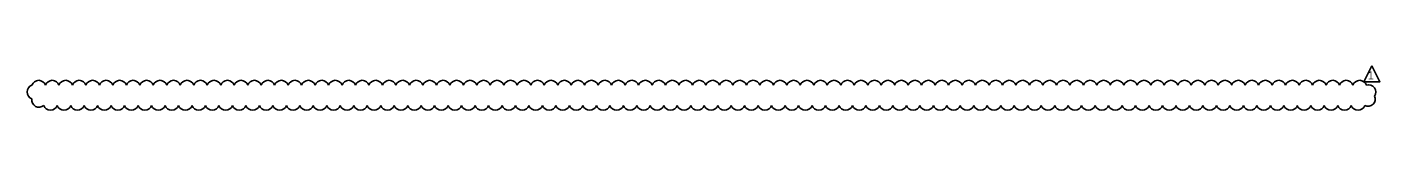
# Model space of a CAD drawing. Extents: x -156 to 77, y 0 to 24.
# Drawn here: x -156.35 to -132.68, y 23.65 to 24.43 of the extents above; entities that cross this region are included whole.
import ezdxf

# ---------------------------------------------------------------- set-up
doc = ezdxf.new("R2010")
doc.units = 0
doc.layers.add('SH_Text', color=7, linetype='Continuous')

msp = doc.modelspace()

# ---------------------------------------------------------------- linework, layer by layer
at = {"layer": 'SH_Text'}
msp.add_lwpolyline([(-132.816, 24.427), (-132.956, 24.147), (-132.676, 24.147)], close=True, dxfattribs=at)
for centre, start, end in [((-156.146, 24.047), 17.5, 162.5), ((-155.91, 24.047), 17.5, 162.5), ((-155.674, 24.047), 17.5, 162.5), ((-155.438, 24.047), 17.5, 162.5), ((-155.203, 24.047), 17.5, 162.5), ((-154.967, 24.047), 17.5, 162.5), ((-154.731, 24.047), 17.5, 162.5), ((-154.495, 24.047), 17.5, 162.5), ((-154.259, 24.047), 17.5, 162.5), ((-154.023, 24.047), 17.5, 162.5), ((-153.787, 24.047), 17.5, 162.5), ((-153.551, 24.047), 17.5, 162.5), ((-153.316, 24.047), 17.5, 162.5), ((-153.08, 24.047), 17.5, 162.5), ((-152.844, 24.047), 17.5, 162.5), ((-152.608, 24.047), 17.5, 162.5), ((-152.372, 24.047), 17.5, 162.5), ((-152.136, 24.047), 17.5, 162.5), ((-151.9, 24.047), 17.5, 162.5), ((-151.664, 24.047), 17.5, 162.5), ((-151.428, 24.047), 17.5, 162.5), ((-151.193, 24.047), 17.5, 162.5), ((-150.957, 24.047), 17.5, 162.5), ((-150.721, 24.047), 17.5, 162.5), ((-150.485, 24.047), 17.5, 162.5), ((-150.249, 24.047), 17.5, 162.5), ((-150.013, 24.047), 17.5, 162.5), ((-149.777, 24.047), 17.5, 162.5), ((-149.541, 24.047), 17.5, 162.5), ((-149.306, 24.047), 17.5, 162.5), ((-149.07, 24.047), 17.5, 162.5), ((-148.834, 24.047), 17.5, 162.5), ((-148.598, 24.047), 17.5, 162.5), ((-148.362, 24.047), 17.5, 162.5), ((-148.126, 24.047), 17.5, 162.5), ((-147.89, 24.047), 17.5, 162.5), ((-147.654, 24.047), 17.5, 162.5), ((-147.418, 24.047), 17.5, 162.5), ((-147.183, 24.047), 17.5, 162.5), ((-146.947, 24.047), 17.5, 162.5), ((-146.711, 24.047), 17.5, 162.5), ((-146.475, 24.047), 17.5, 162.5), ((-146.239, 24.047), 17.5, 162.5), ((-146.003, 24.047), 17.5, 162.5), ((-145.767, 24.047), 17.5, 162.5), ((-145.531, 24.047), 17.5, 162.5), ((-145.296, 24.047), 17.5, 162.5), ((-145.06, 24.047), 17.5, 162.5), ((-144.824, 24.047), 17.5, 162.5), ((-144.588, 24.047), 17.5, 162.5), ((-144.352, 24.047), 17.5, 162.5), ((-144.116, 24.047), 17.5, 162.5), ((-143.88, 24.047), 17.5, 162.5), ((-143.644, 24.047), 17.5, 162.5), ((-143.408, 24.047), 17.5, 162.5), ((-143.173, 24.047), 17.5, 162.5), ((-142.937, 24.047), 17.5, 162.5), ((-142.701, 24.047), 17.5, 162.5), ((-142.465, 24.047), 17.5, 162.5), ((-142.229, 24.047), 17.5, 162.5), ((-141.993, 24.047), 17.5, 162.5), ((-141.757, 24.047), 17.5, 162.5), ((-141.521, 24.047), 17.5, 162.5), ((-141.286, 24.047), 17.5, 162.5), ((-141.05, 24.047), 17.5, 162.5), ((-140.814, 24.047), 17.5, 162.5), ((-140.578, 24.047), 17.5, 162.5), ((-140.342, 24.047), 17.5, 162.5), ((-140.106, 24.047), 17.5, 162.5), ((-139.87, 24.047), 17.5, 162.5), ((-139.634, 24.047), 17.5, 162.5), ((-139.398, 24.047), 17.5, 162.5), ((-139.163, 24.047), 17.5, 162.5), ((-138.927, 24.047), 17.5, 162.5), ((-138.691, 24.047), 17.5, 162.5), ((-138.455, 24.047), 17.5, 162.5), ((-138.219, 24.047), 17.5, 162.5), ((-137.983, 24.047), 17.5, 162.5), ((-137.747, 24.047), 17.5, 162.5), ((-137.511, 24.047), 17.5, 162.5), ((-137.276, 24.047), 17.5, 162.5), ((-137.04, 24.047), 17.5, 162.5), ((-136.804, 24.047), 17.5, 162.5), ((-136.568, 24.047), 17.5, 162.5), ((-136.332, 24.047), 17.5, 162.5), ((-136.096, 24.047), 17.5, 162.5), ((-135.86, 24.047), 17.5, 162.5), ((-135.624, 24.047), 17.5, 162.5), ((-135.388, 24.047), 17.5, 162.5), ((-135.153, 24.047), 17.5, 162.5), ((-134.917, 24.047), 17.5, 162.5), ((-134.681, 24.047), 17.5, 162.5), ((-134.445, 24.047), 17.5, 162.5), ((-134.209, 24.047), 17.5, 162.5), ((-133.973, 24.047), 17.5, 162.5), ((-133.737, 24.047), 17.5, 162.5), ((-133.501, 24.047), 17.5, 162.5), ((-133.266, 24.047), 17.5, 162.5), ((-133.03, 24.047), 17.5, 162.5), ((-156.227, 23.967), 107.5, 252.5), ((-132.871, 23.968), 324.1437, 109.1437), ((-156.143, 23.823), 168.0907, 313.0907), ((-155.941, 23.77), 197.5, 342.5), ((-155.705, 23.77), 197.5, 342.5), ((-155.469, 23.77), 197.5, 342.5), ((-155.233, 23.77), 197.5, 342.5), ((-154.997, 23.77), 197.5, 342.5), ((-154.761, 23.77), 197.5, 342.5), ((-154.525, 23.77), 197.5, 342.5), ((-154.289, 23.77), 197.5, 342.5), ((-154.054, 23.77), 197.5, 342.5), ((-153.818, 23.77), 197.5, 342.5), ((-153.582, 23.77), 197.5, 342.5), ((-153.346, 23.77), 197.5, 342.5), ((-153.11, 23.77), 197.5, 342.5), ((-152.874, 23.77), 197.5, 342.5), ((-152.638, 23.77), 197.5, 342.5), ((-152.402, 23.77), 197.5, 342.5), ((-152.167, 23.77), 197.5, 342.5), ((-151.931, 23.77), 197.5, 342.5), ((-151.695, 23.77), 197.5, 342.5), ((-151.459, 23.77), 197.5, 342.5), ((-151.223, 23.77), 197.5, 342.5), ((-150.987, 23.77), 197.5, 342.5), ((-150.751, 23.77), 197.5, 342.5), ((-150.515, 23.77), 197.5, 342.5), ((-150.279, 23.77), 197.5, 342.5), ((-150.044, 23.77), 197.5, 342.5), ((-149.808, 23.77), 197.5, 342.5), ((-149.572, 23.77), 197.5, 342.5), ((-149.336, 23.77), 197.5, 342.5), ((-149.1, 23.77), 197.5, 342.5), ((-148.864, 23.77), 197.5, 342.5), ((-148.628, 23.77), 197.5, 342.5), ((-148.392, 23.77), 197.5, 342.5), ((-148.157, 23.77), 197.5, 342.5), ((-147.921, 23.77), 197.5, 342.5), ((-147.685, 23.77), 197.5, 342.5), ((-147.449, 23.77), 197.5, 342.5), ((-147.213, 23.77), 197.5, 342.5), ((-146.977, 23.77), 197.5, 342.5), ((-146.741, 23.77), 197.5, 342.5), ((-146.505, 23.77), 197.5, 342.5), ((-146.269, 23.77), 197.5, 342.5), ((-146.034, 23.77), 197.5, 342.5), ((-145.798, 23.77), 197.5, 342.5), ((-145.562, 23.77), 197.5, 342.5), ((-145.326, 23.77), 197.5, 342.5), ((-145.09, 23.77), 197.5, 342.5), ((-144.854, 23.77), 197.5, 342.5), ((-144.618, 23.77), 197.5, 342.5), ((-144.382, 23.77), 197.5, 342.5), ((-144.147, 23.77), 197.5, 342.5), ((-143.911, 23.77), 197.5, 342.5), ((-143.675, 23.77), 197.5, 342.5), ((-143.439, 23.77), 197.5, 342.5), ((-143.203, 23.77), 197.5, 342.5), ((-142.967, 23.77), 197.5, 342.5), ((-142.731, 23.77), 197.5, 342.5), ((-142.495, 23.77), 197.5, 342.5), ((-142.259, 23.77), 197.5, 342.5), ((-142.024, 23.77), 197.5, 342.5), ((-141.788, 23.77), 197.5, 342.5), ((-141.552, 23.77), 197.5, 342.5), ((-141.316, 23.77), 197.5, 342.5), ((-141.08, 23.77), 197.5, 342.5), ((-140.844, 23.77), 197.5, 342.5), ((-140.608, 23.77), 197.5, 342.5), ((-140.372, 23.77), 197.5, 342.5), ((-140.137, 23.77), 197.5, 342.5), ((-139.901, 23.77), 197.5, 342.5), ((-139.665, 23.77), 197.5, 342.5), ((-139.429, 23.77), 197.5, 342.5), ((-139.193, 23.77), 197.5, 342.5), ((-138.957, 23.77), 197.5, 342.5), ((-138.721, 23.77), 197.5, 342.5), ((-138.485, 23.77), 197.5, 342.5), ((-138.249, 23.77), 197.5, 342.5), ((-138.014, 23.77), 197.5, 342.5), ((-137.778, 23.77), 197.5, 342.5), ((-137.542, 23.77), 197.5, 342.5), ((-137.306, 23.77), 197.5, 342.5), ((-137.07, 23.77), 197.5, 342.5), ((-136.834, 23.77), 197.5, 342.5), ((-136.598, 23.77), 197.5, 342.5), ((-136.362, 23.77), 197.5, 342.5), ((-136.127, 23.77), 197.5, 342.5), ((-135.891, 23.77), 197.5, 342.5), ((-135.655, 23.77), 197.5, 342.5), ((-135.419, 23.77), 197.5, 342.5), ((-135.183, 23.77), 197.5, 342.5), ((-134.947, 23.77), 197.5, 342.5), ((-134.711, 23.77), 197.5, 342.5), ((-134.475, 23.77), 197.5, 342.5), ((-134.239, 23.77), 197.5, 342.5), ((-134.004, 23.77), 197.5, 342.5), ((-133.768, 23.77), 197.5, 342.5), ((-133.532, 23.77), 197.5, 342.5), ((-133.296, 23.77), 197.5, 342.5), ((-133.06, 23.77), 197.5, 342.5), ((-132.882, 23.841), 241.0263, 26.0263)]:
    msp.add_arc(centre, 0.124, start, end, dxfattribs=at)

# ---------------------------------------------------------------- texts
msp.add_text('1', height=0.14, dxfattribs=at).set_placement((-132.888, 24.187))

doc.saveas('drawing.dxf')
